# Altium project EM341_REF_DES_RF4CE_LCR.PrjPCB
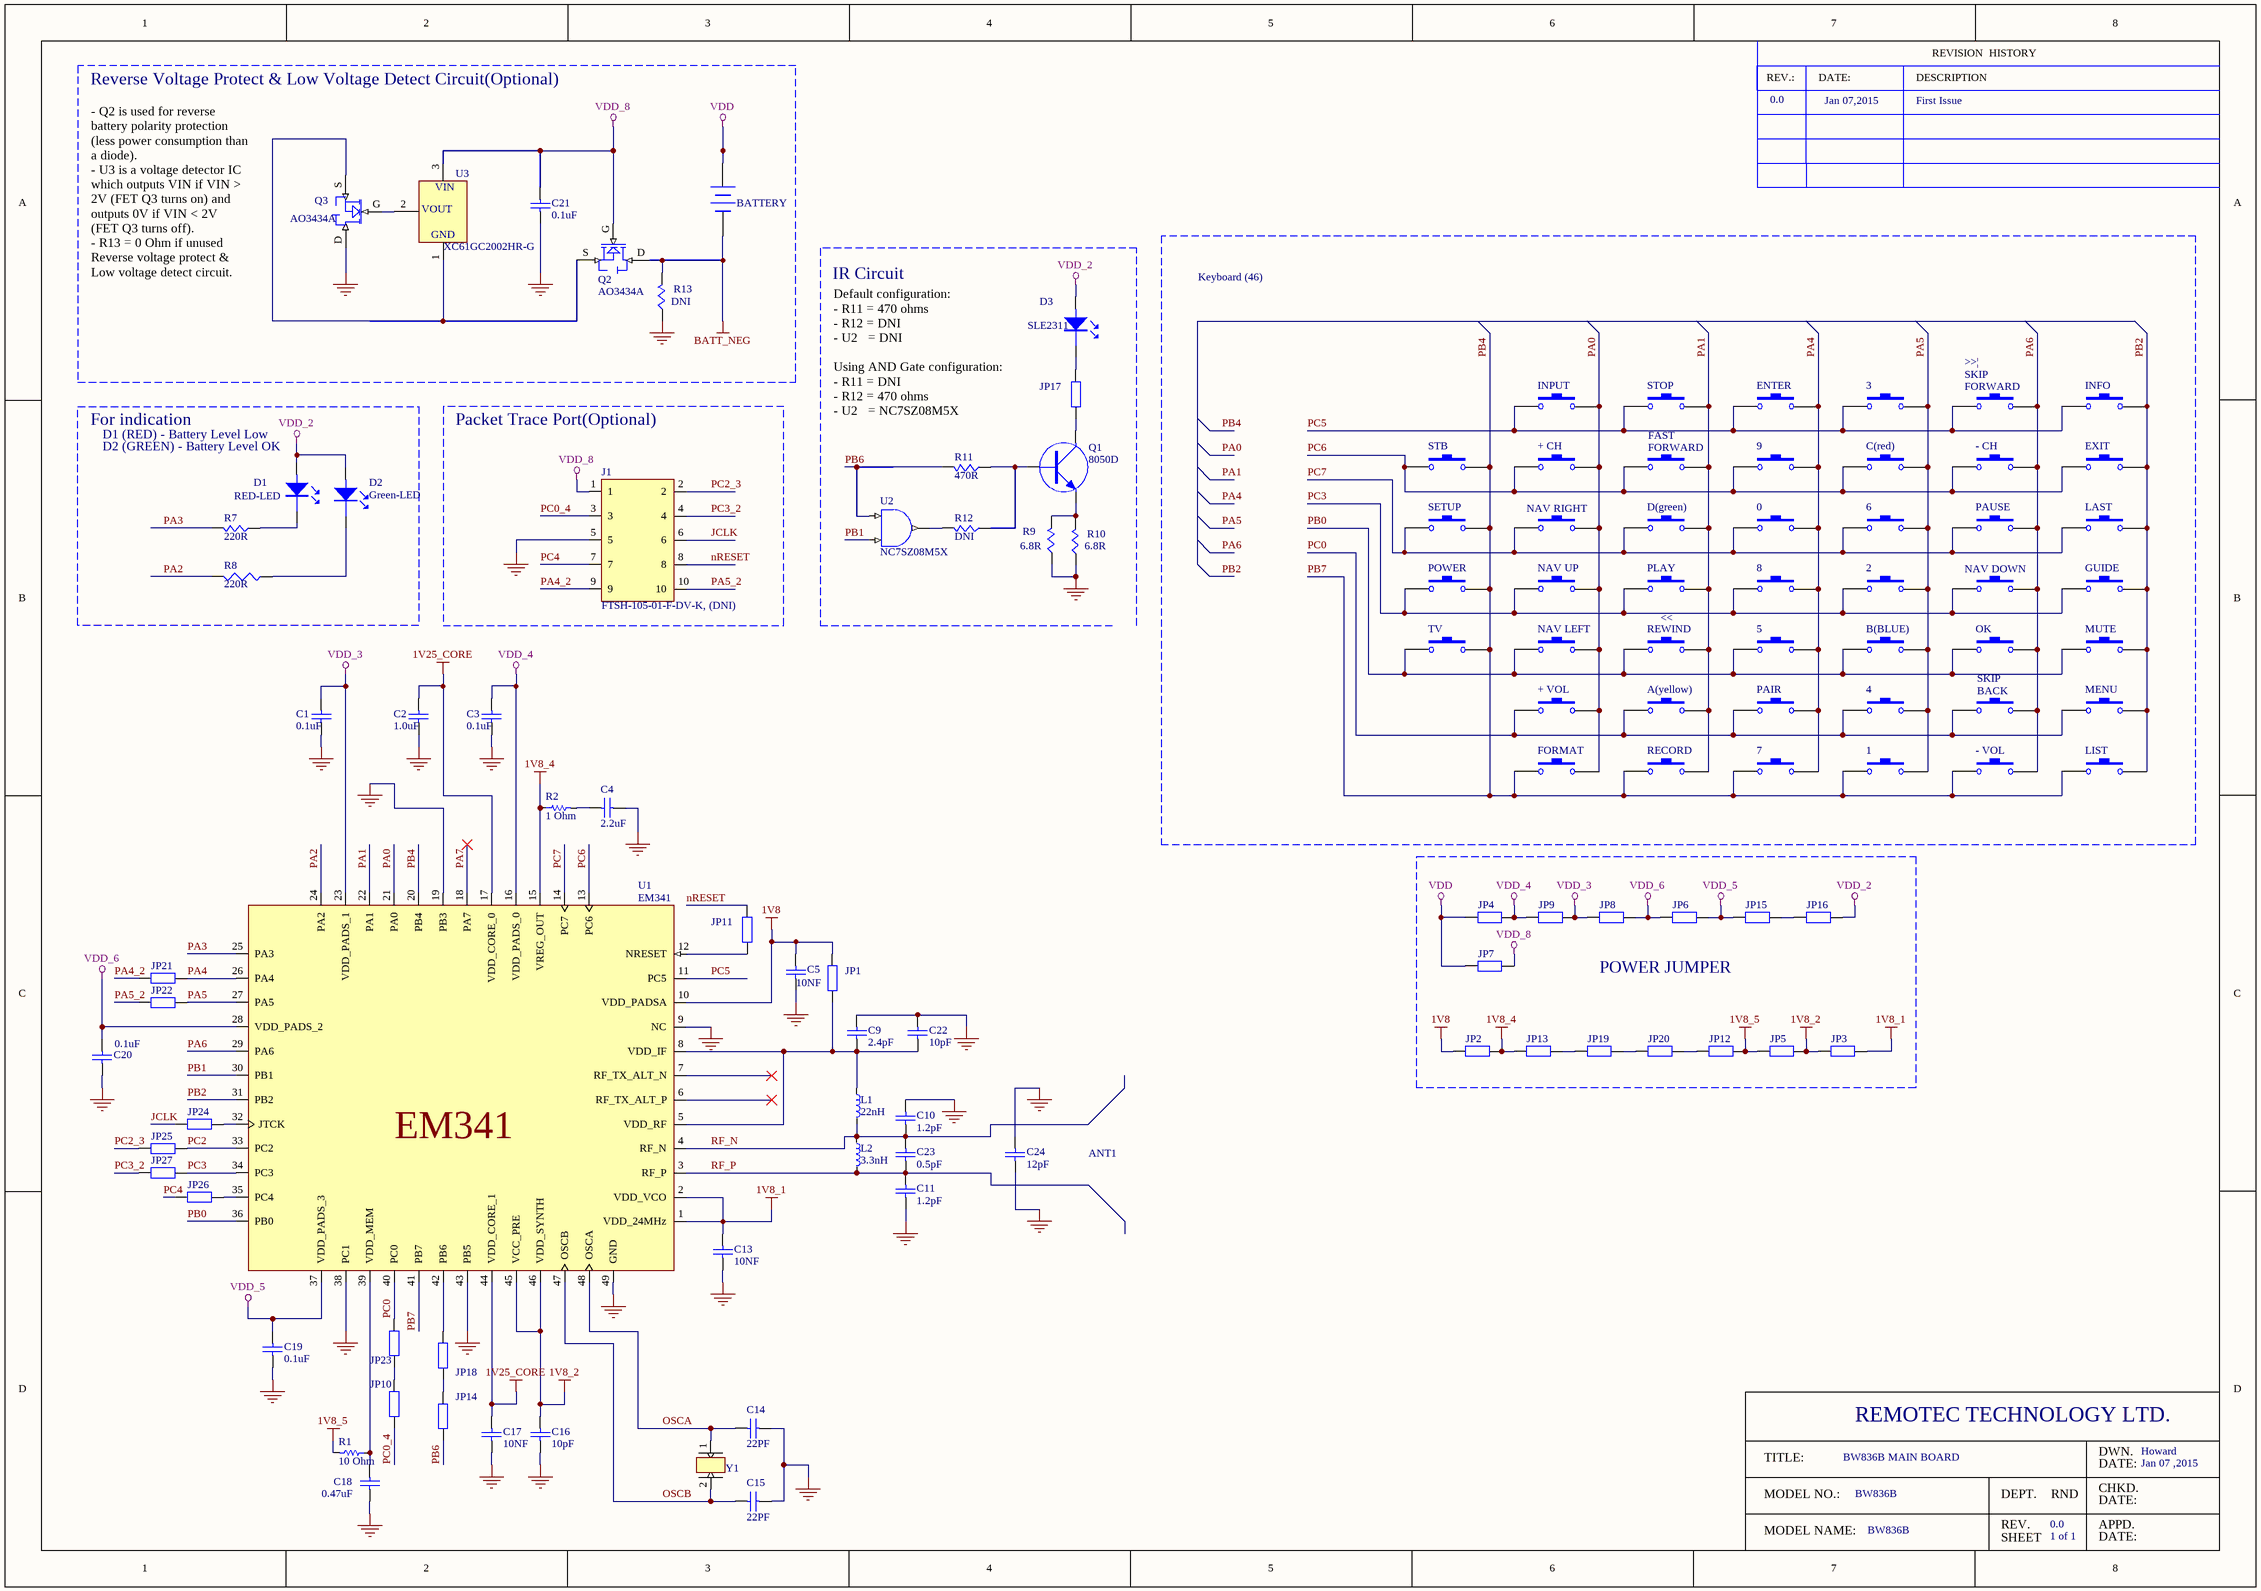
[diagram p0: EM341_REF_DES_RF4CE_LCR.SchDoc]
XYReportName: EM341_REF_DES_RF4CE_LCR_A0_XYR; Title: EM341 Dipole Antenna RF4CE 1-Layer Remote Control; SchematicName: EM341_REF_DES_RF4CE_LCR_A0_SCH; FabPrintName: EM341_REF_DES_RF4CE_LCR_A0_FAB; Company Web Site: www.silabs.com; Company Tel: 617-951-0200; Company Design Group: MCU & WMN Support Group; Company Address 3: Boston, MA 02210; Company Address 2: 4th Floor; Company Address 1: 343 Congress St; ClassName: PCB Only; CamPrintName: EM341_REF_DES_RF4CE_LCR_A0_CAM; Board Rev: A0; Board No: EM341_REF_DES_RF4CE_LCR; AssemblyPrintName: EM341_REF_DES_RF4CE_LCR_A0_ASM
1 sheet, 118 parts. Net scope: global (net labels, ports and power ports of the same name join across sheets).
Board file: EM341_REF_DES_RF4CE_LCR.PcbDoc

## Sheet EM341_REF_DES_RF4CE_LCR.SchDoc: EM341 Dipole Antenna RF4CE 1-Layer Remote Control
size 469 x 330 mm; SheetNumber: 0; SheetTotal: 0; PageSetup: Record=PageOptions¦SelectedOnly=False¦CenterHorizontal=True¦CenterVertical=True¦PrintScale=0.62¦XCorrection=1.00¦YCorrection=1.00¦PrintKind=0¦BorderSize=5000000¦LeftOffset=0¦BottomOffset=0¦Orientation=2¦PaperLength=1000¦PaperWidth=1000¦Scale=100¦PaperSource=7¦PrintQuality=-4¦MediaType=1¦DitherType=10¦PaperKind=A4¦PrintScaleMode=1

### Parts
0  (no value)  [Key-S]
1  (no value)  [Key-S]
2  (no value)  [Key-S]
3  (no value)  [Key-S]
4  (no value)  [Key-S]
5  (no value)  [Key-S]
6  (no value)  [Key-S]
7  (no value)  [Key-S]
8  (no value)  [Key-S]
9  (no value)  [Key-S]
+_CH  (no value)  [Key-S]
+_VOL  (no value)  [Key-S]
-_CH  (no value)  [Key-S]
-_VOL  (no value)  [Key-S]
A(yellow)  (no value)  [Key-S]
B(BLUE)  (no value)  [Key-S]
BACK  (no value)  [Key-S]
BAT1  BATTERY  [Key-S]
C1  0.1uF  [C_0402]
C2  1.0uF  [C_0603]
C3  0.1uF  [C_0402]
C4  2.2uF  [C_0603]
C5  10NF  [C_0402]
C9  2.4pF  [C_0402]
C10  1.2pF  [C_0402]
C11  1.2pF  [C_0402]
C13  10NF  [C_0402]
C14  22PF  [C_0402]
C15  22PF  [C_0402]
C16  10pF  [C_0402]
C17  10NF  [C_0402]
C18  0.47uF  [C_0402]
C19  0.1uF  [C_0402]
C20  0.1uF  [C_0402]
C21  0.1uF  [C_0402]
C22  10pF  [C_0402]
C23  0.5pF  [C_0402]
C24  12pF  [C_0402]
C(red)  (no value)  [Key-S]
D1  RED-LED  [2_LED]
D2  Green-LED  [0805-L]
D3  SLE2311  [0805-L]
D(green)  (no value)  [Key-S]
ENTER  (no value)  [Key-S]
EXIT  (no value)  [Key-S]
FAST  (no value)  [Key-S]
FORMAT  (no value)  [Key-S]
GUIDE  (no value)  [Key-S]
INFO  (no value)  [Key-S]
INPUT  (no value)  [Key-S]
J1  FTSH-105-01-F-DV-K, (DNI)  [2*5 Pin_1.27mm]
JP1  0  [AXIAL-0.4]  (value not drawn)
JP2  0  [AXIAL-0.4]  (value not drawn)
JP3  0  [AXIAL-0.4]  (value not drawn)
JP4  0  [AXIAL-0.4]  (value not drawn)
JP5  0  [AXIAL-0.4]  (value not drawn)
JP6  0  [AXIAL-0.4]  (value not drawn)
JP7  0  [AXIAL-0.4]  (value not drawn)
JP8  0  [AXIAL-0.4]  (value not drawn)
JP9  0  [AXIAL-0.4]  (value not drawn)
JP10  0  [AXIAL-0.4]  (value not drawn)
JP11  0  [AXIAL-0.4]  (value not drawn)
JP12  0  [AXIAL-0.4]  (value not drawn)
JP13  0  [AXIAL-0.4]  (value not drawn)
JP14  0  [AXIAL-0.4]  (value not drawn)
JP15  0  [AXIAL-0.4]  (value not drawn)
JP16  0  [AXIAL-0.4]  (value not drawn)
JP17  0  [AXIAL-0.4]  (value not drawn)
JP18  0  [AXIAL-0.4]  (value not drawn)
JP19  0  [AXIAL-0.4]  (value not drawn)
JP20  0  [AXIAL-0.4]  (value not drawn)
JP21  0  [AXIAL-0.4]  (value not drawn)
JP22  0  [AXIAL-0.4]  (value not drawn)
JP23  0  [AXIAL-0.4]  (value not drawn)
JP24  0  [AXIAL-0.4]  (value not drawn)
JP25  0  [AXIAL-0.4]  (value not drawn)
JP26  0  [AXIAL-0.4]  (value not drawn)
JP27  0  [AXIAL-0.4]  (value not drawn)
L1  22nH  [L_0402]
L2  3.3nH  [L_0402]
LAST  (no value)  [Key-S]
LIST  (no value)  [Key-S]
MENU  (no value)  [Key-S]
MUTE  (no value)  [Key-S]
NAV_DOWN  (no value)  [Key-S]
NAV_LEFT  (no value)  [Key-S]
NAV_RIGHT  (no value)  [Key-S]
NAV_UP  (no value)  [Key-S]
OK  (no value)  [Key-S]
PAIR  (no value)  [Key-S]
PAUSE  (no value)  [Key-S]
PLAY  (no value)  [Key-S]
POWER  (no value)  [Key-S]
Q1  8050D  [SMDPN]
Q2  AO3434A  [SMDPN]
Q3  AO3434A  [SMDPN]
R1  10 Ohm  [R_0402]
R2  1 Ohm  [R_0402]
R7  220R  [R_0402]
R8  220R  [R_0402]
R9  6.8R  [R_0402]
R10  6.8R  [R_0402]
R11  470R  [R_0402]
R12  DNI  [R_0402]
R13  DNI  [R_0402]
RECORD  (no value)  [Key-S]
REWIND  (no value)  [Key-S]
SETUP  (no value)  [Key-S]
SKIP  (no value)  [Key-S]
STB  (no value)  [Key-S]
STOP  (no value)  [Key-S]
TV  (no value)  [Key-S]
TXT1  BORDER2  (value not drawn)
TXT2  BORDER1  (value not drawn)
U1  EM341  [EM341_1-Layer]
U2  NC7SZ08M5X  [SOT23-5]
U3  XC61GC2002HR-G  [USP-3]
Y1  24.000MHZ, 18PF LOAD  [HC-49-TH]  (value not drawn)

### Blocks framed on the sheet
For indication: D1 D2 R7 R8
Packet Trace Port(Optional): J1
POWER JUMPER: JP2-JP9 JP12 JP13 JP15 JP16 JP19 JP20

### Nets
1V8: C5.1 JP1.2 JP2.2 U1.10(VDD_PADSA)
1V8_1: C13.1 JP3.2 U1.1(VDD_24MHz) U1.2(VDD_VCO)
1V8_2: C16.1 JP3.1 JP5.2 U1.45(VCC_PRE) U1.46(VDD_SYNTH)
1V8_4: JP2.1 JP13.1 R2.1 U1.15(VREG_OUT)
1V8_5: JP5.1 JP12.2 R1.2
1V25_CORE: C2.1 C17.1 U1.17(VDD_CORE_0) U1.44(VDD_CORE_1)
BATT_NEG: BAT1.2(-) Q2.D R13.2
GND: C1.2 C2.2 C3.2 C4.2 C5.2 C9.1 C10.2 C11.2 C13.2 C14.2 C15.2 C16.2 C17.2 C18.2 C19.2 C20.2 C21.2 C22.2 C24.1 C24.2 J1.5 Q3.D R9.1 R10.1 R13.1 U1.9(NC) U1.19(PB3) U1.38(PC1) U1.43(PB5) U1.49(GND)
VDD: BAT1.1(+) JP4.2 JP7.2
VDD_2: D1.A D2.A D3.A JP16.2
VDD_3: C1.1 JP8.1 JP9.2 U1.23(VDD_PADS_1)
VDD_4: C3.1 JP4.1 JP9.1 U1.16(VDD_PADS_0)
VDD_5: C19.1 JP6.2 JP15.1 U1.37(VDD_PADS_3)
VDD_6: C20.1 JP6.1 JP8.2 U1.28(VDD_PADS_2)
VDD_8: C21.1 J1.1 JP7.1 Q2.G U3.3
JCLK: J1.6 JP24.1
nRESET: J1.8 JP11.2
OSCA: C14.1 U1.48(OSCA) Y1.1(OSCB)
OSCB: C15.1 U1.47(OSCB) Y1.2(OSCA)
PA0: +_CH.2 +_VOL.2 FORMAT.2 INPUT.2 NAV_LEFT.2 NAV_RIGHT.2 NAV_UP.2 U1.21(PA0)
PA1: A(yellow).2 D(green).2 FAST.2 PLAY.2 RECORD.2 REWIND.2 STOP.2 U1.22(PA1)
PA2: R8.1 U1.24(PA2)
PA3: R7.2 U1.25(PA3)
PA4: 0.2 5.2 7.2 8.2 9.2 ENTER.2 JP21.2 PAIR.2 U1.26(PA4)
PA4_2: J1.9 JP21.1
PA5: 1.2 2.2 3.2 4.2 6.2 B(BLUE).2 C(red).2 JP22.2 U1.27(PA5)
PA5_2: J1.10 JP22.1
PA6: -_CH.2 -_VOL.2 BACK.2 NAV_DOWN.2 OK.2 PAUSE.2 SKIP.2 U1.29(PA6)
PA7: U1.18(PA7)
PB0: 5.1 B(BLUE).1 MUTE.1 NAV_LEFT.1 OK.1 REWIND.1 TV.1 U1.36(PB0)
PB1: U1.30(PB1) U2.2(B)
PB2: EXIT.2 GUIDE.2 INFO.2 LAST.2 LIST.2 MENU.2 MUTE.2 U1.31(PB2)
PB4: 1.1 7.1 -_VOL.1 FORMAT.1 LIST.1 POWER.2 RECORD.1 SETUP.2 STB.2 TV.2 U1.20(PB4) U1.41(PB7)  [also labelled PB7]
PB6: JP14.1 R11.2 U2.1(A)
PC0: 4.1 +_VOL.1 A(yellow).1 BACK.1 JP23.2 MENU.1 PAIR.1 U1.40(PC0)
PC0_4: J1.3 JP10.1
PC2: JP25.2 U1.33(PC2)
PC2_3: J1.2 JP25.1
PC3: 2.1 8.1 GUIDE.1 JP27.2 NAV_DOWN.1 NAV_UP.1 PLAY.1 POWER.1 U1.34(PC3)
PC3_2: J1.4 JP27.1
PC4: J1.7 JP26.1
PC5: 3.1 ENTER.1 INFO.1 INPUT.1 SKIP.1 STOP.1 U1.11(PC5)
PC6: 9.1 +_CH.1 -_CH.1 C(red).1 EXIT.1 FAST.1 STB.1 U1.13(PC6)
PC7: 0.1 6.1 D(green).1 LAST.1 NAV_RIGHT.1 PAUSE.1 SETUP.1 U1.14(PC7)
RF_N: C10.1 C23.1 L1.2 L2.1 U1.4(RF_N)
RF_P: C11.1 C23.2 L2.2 U1.3(RF_P)
NetC4_1: C4.1 R2.2
NetC9_2: C9.2 C22.1 JP1.1 L1.1 U1.5(VDD_RF) U1.8(VDD_IF)
NetC18_1: C18.1 R1.1 U1.39(VDD_MEM)
NetD1_K: D1.K R7.1
NetD2_K: D2.K R8.2
NetD3_K: D3.K JP17.2
NetJP10_2: JP10.2 JP23.1
NetJP11_1: JP11.1 U1.12(NRESET)
NetJP12_1: JP12.1 JP20.2
NetJP13_2: JP13.2 JP19.1
NetJP14_2: JP14.2 JP18.1
NetJP15_2: JP15.2 JP16.1
NetJP17_1: JP17.1 Q1.2(C)
NetJP18_2: JP18.2 U1.42(PB6)
NetJP19_2: JP19.2 JP20.1
NetJP24_2: JP24.2 U1.32(JTCK)
NetJP26_2: JP26.2 U1.35(PC4)
NetQ1_1: Q1.1(B) R11.1 R12.1
NetQ1_3: Q1.3(E) R9.2 R10.2
NetQ2_S: Q2.S Q3.S U3.1
NetQ3_G: Q3.G U3.2
NetR12_2: R12.2 U2.3(Y)

Not connected (* = marked no-connect by the designer): U1 6(RF_TX_ALT_P)* 7(RF_TX_ALT_N)*

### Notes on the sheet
- Reverse Voltage Protect & Low Voltage Detect Circuit(Optional)
- 0.0
- Jan 07,2015
- First Issue
- - Q2 is used for reverse battery polarity protection (less power consumption than a diode).
  - U3 is a voltage detector IC which outputs VIN if VIN > 2V (FET Q3 turns on) and outputs 0V if VIN < 2V (FET Q3 turns off).
  - R13 = 0 Ohm if unused Reverse voltage protect & Low voltage detect circuit.
- IR Circuit
- Keyboard (46)
- (near SKIP) FORWARD
- (near SKIP) >>¦
- (near D1) D1 (RED) - Battery Level Low
- (near D1) D2 (GREEN) - Battery Level OK
- Default configuration:
  - R11 = 470 ohms
  - R12 = DNI
  - U2   = DNI
  Using AND Gate configuration:
  - R11 = DNI
  - R12 = 470 ohms
  - U2   = NC7SZ08M5X
- (near FAST) FORWARD
- <<
- SKIP
- ANT1
- REMOTEC TECHNOLOGY LTD.
- BW836B MAIN BOARD
- Howard
- Jan 07 ,2015
- BW836B
- 1 of 1

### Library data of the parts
0-9 +_CH +_VOL -_CH -_VOL A(yellow) B(BLUE) BACK C(red) D(green) ENTER EXIT FAST FORMAT GUIDE INFO INPUT LAST LIST MENU MUTE NAV_DOWN NAV_LEFT NAV_RIGHT NAV_UP OK PAIR PAUSE PLAY POWER RECORD REWIND SETUP SKIP STB STOP TV = SW-PB: Switch
C1 C3 C19-C21 = EMBER_CAPACITOR.1: Part Description: CAPACITOR, CERAMIC, 0.1UF, +/-10%, 6.3V, -55C TO 125C, X7R, 0402 (1005 METRIC); MANUFACTURER: MURATA; PART_NUMBER: GRM155R70J104KA01D; EMBER_P/N: 550-0034-000; VOLTAGE: 6.3V; TOLERANCE: +/-10%; Temperature Coefficient: -55C to 125C, X7R
C2 = EMBER_CAPACITOR.1: Part Description: CAPACITOR, CERAMIC, 1.0UF, +/-10%, 10V, -55C TO 125C, X7R, 0603 (1608 METRIC); MANUFACTURER: TAIYO YUDEN LTD; PART_NUMBER: LMK107B7105KA-T; EMBER_P/N: 550-0033-000; VOLTAGE: 10V; TOLERANCE: +/-10%; Temperature Coefficient: -55C to 125C, X7R
C4 = EMBER_CAPACITOR.1: Part Description: CAPACITOR, CERAMIC, 2.2UF, +/-10%, 6.3V, -55C TO 125C, X7R, 0603 (1608 METRIC); MANUFACTURER: MURATA; PART_NUMBER: CL10B225KQ8NNNC; EMBER_P/N: 550-0038-000; VOLTAGE: 6.3V; TOLERANCE: +/-10%; Temperature Coefficient: -55C to 125C, X7R
C5 = EMBER_CAPACITOR.1: Part Description: CAPACITOR, CERAMIC, 10NF, +/-10%, 6.3V, -55C TO 125C, X7R, 0402 (1005 METRIC); MANUFACTURER: MURATA; PART_NUMBER: GRM155R70J103KA01D; EMBER_P/N: 550-0036-000; TOLERANCE: +/-10%; Temperature Coefficient: -55C to 125C, X7R; VOLTAGE: 6.3V
C9 = EMBER_CAPACITOR.1: Part Description: CAPACITOR, CERAMIC, 1.6PF, +/-0.1PF, 50V, -55C TO 125C, C0G, NP0, 0402 (1005 METRIC); MANUFACTURER: MURATA; PART_NUMBER: GRM1555C1H1R6BA01D; EMBER_P/N: 550-0044-000; VOLTAGE: 50V; TOLERANCE: +/-0.1pF; Temperature Coefficient: -55C to 125C, C0G, NP0
C10 = EMBER_CAPACITOR.1: Part Description: CAPACITOR, CERAMIC, 1PF, +/-0.25PF, 50V, -55C TO 125C, C0G, NP0, 0402 (1005 METRIC); MANUFACTURER: SAMSUNG ELECTRONICS; PART_NUMBER: CL05C010CB5NNNC; EMBER_P/N: 550-0040-000; VOLTAGE: 50V; TOLERANCE: +/-0.25pF; Temperature Coefficient: -55C to 125C, C0G, NP0
C11 = EMBER_CAPACITOR.1: Part Description: CAPACITOR, CERAMIC, 1.8PF, +/-0.25PF, 50V, -55C TO 125C, C0G, NP0, 0402 (1005 METRIC); MANUFACTURER: MURATA; PART_NUMBER: GRM1555C1H1R8CA01D; EMBER_P/N: 550-1P8A-050; VOLTAGE: 50V; TOLERANCE: +/-0.25pF; Temperature Coefficient: -55C to 125C, C0G, NP0
C13 C17 = EMBER_CAPACITOR.1: Part Description: CAPACITOR, CERAMIC, 10NF, +/-10%, 6.3V, -55C TO 125C, X7R, 0402 (1005 METRIC); MANUFACTURER: MURATA; PART_NUMBER: GRM155R70J103KA01D; EMBER_P/N: 550-0036-000; VOLTAGE: 6.3V; TOLERANCE: +/-10%; Temperature Coefficient: -55C to 125C, X7R
C14 C15 = EMBER_CAPACITOR.1: Part Description: CAPACITOR, CERAMIC, 22PF, +/-5%, 50V, -55C TO 125C, 0402 (1005 METRIC); MANUFACTURER: MURATA; PART_NUMBER: GRM1555C1H220JA01D; EMBER_P/N: 550-2201-050; VOLTAGE: 50V; TOLERANCE: +/-5%; Temperature Coefficient: -55C to 125C
C16 = EMBER_CAPACITOR.1: Part Description: CAPACITOR, CERAMIC, 10PF, +/-5%, 50V, -55C TO 125C, 0402 (1005 METRIC); MANUFACTURER: MURATA; PART_NUMBER: GRM1555C1H100JA01D; EMBER_P/N: 550-1001-050; VOLTAGE: 50V; TOLERANCE: +/-5%; Temperature Coefficient: -55C to 125C
C18 = EMBER_CAPACITOR.1: Part Description: CAPACITOR, CERAMIC, 0.47UF, +/- 10%, 6.3V, -55C TO 85C, X5R, 0402 (1005 METRIC); MANUFACTURER: MURATA; PART_NUMBER: GRM155R60J474KE19D; EMBER_P/N: 550-0037-000; VOLTAGE: 6.3V; TOLERANCE: +/- 10%; Temperature Coefficient: -55C to 85C, X5R
C22 C24 = EMBER_CAPACITOR.1: Part Description: CAPACITOR, 0402, DO NOT INSTALL; EMBER_P/N: 550-0000-DNI
C23 = EMBER_CAPACITOR.1
D1-D3 = LED: pin to pad: A>1 K>2
J1 = 610_0045_000_HEADER_10P_D_050.1: CONNECTOR, HEADER, SHROUDED, 10 POSITION, DUAL ROW, VERTICAL, 0.050"; Part Description: CONNECTOR, HEADER, FTSH-105-01-F-DV-K, (DNI), 10 POSITION, DUAL ROW, VERTICAL, 0.050IN; MANUFACTURER: SAMTEC; PART_NUMBER: FTSH-105-01-L-DV-K; EMBER_P/N: 610-0045-000-DNI
JP1-JP27 = Res2: Resistor; Value: 1K
L1 L2 = EMBER_INDUCTOR: Design Placeholder; Part Description: INDUCTOR, MULTI-LAYER FILM, 3.9NH, +/-0.3NH, 450MA, -40C TO 85C, 0603 (1608 METRIC); MANUFACTURER: MURATA; PART_NUMBER: LQG18HN3N9S00D; EMBER_P/N: 566-3N9S-000; Current Rating: 450mA; TOLERANCE: +/-0.3NH; Temperature Coefficient: -40C to 85C
Q1 = NPN: NPN Transistor; pin to pad: 2>3 3>2
Q2 Q3 = MOSFET DUAL G/N: pin to pad: D>3 G>1 S>2
R1 = EMBER_RESISTOR.1: Part Description: RESISTOR, THICK FILM, 10 OHM, +/-1%, 0.1W, 1/10W, 0402 (1005 METRIC); MANUFACTURER: PANASONIC ECG; PART_NUMBER: ERJ-2RKF10R0X; EMBER_P/N: 555-1001-010; POWER: 0.1W, 1/10W; TOLERANCE: +/-1%; Temperature Coefficient: +/-100ppm/C
R2 = EMBER_RESISTOR.1
R7 R9-R13 = R1
R8 = RES1
U2 = AND: AND Gate; pin to pad: 3>4
U3 = VOLT_DETECTOR
Y1 = 565-2400-001_AT49_SMD: OSCILLATOR, CRYSTAL, 24.000MHZ, 18PF LOAD, +/-10PPM TOLERANCE, +/-25PPM STABILITY, -40C TO 85C, AT49; MANUFACTURER: ABRACON, ABRACON, ABRACON, ILSI AMERICA, AEL CRYSTALS LTD; PART_NUMBER: ABLS-24.000MHZ-D-R60-1-W-T, ABLS-24.000MHZ-D1X-T, ABLS-438-24.000MHZ-T, HC49USM-24.000000M-2435, X24M000000S067; EMBER_P/N: 565-2400-009

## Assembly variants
ReferenceDesign4-Layer_PCBnnnn: not fitted AT1 LOGO1 PCB2 R3 R5 R7 X1
Variant of ReferenceDesign4-Layer_PCBnnnn: not fitted AT1 LOGO1 PCB2 R3 R5 R7 X1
